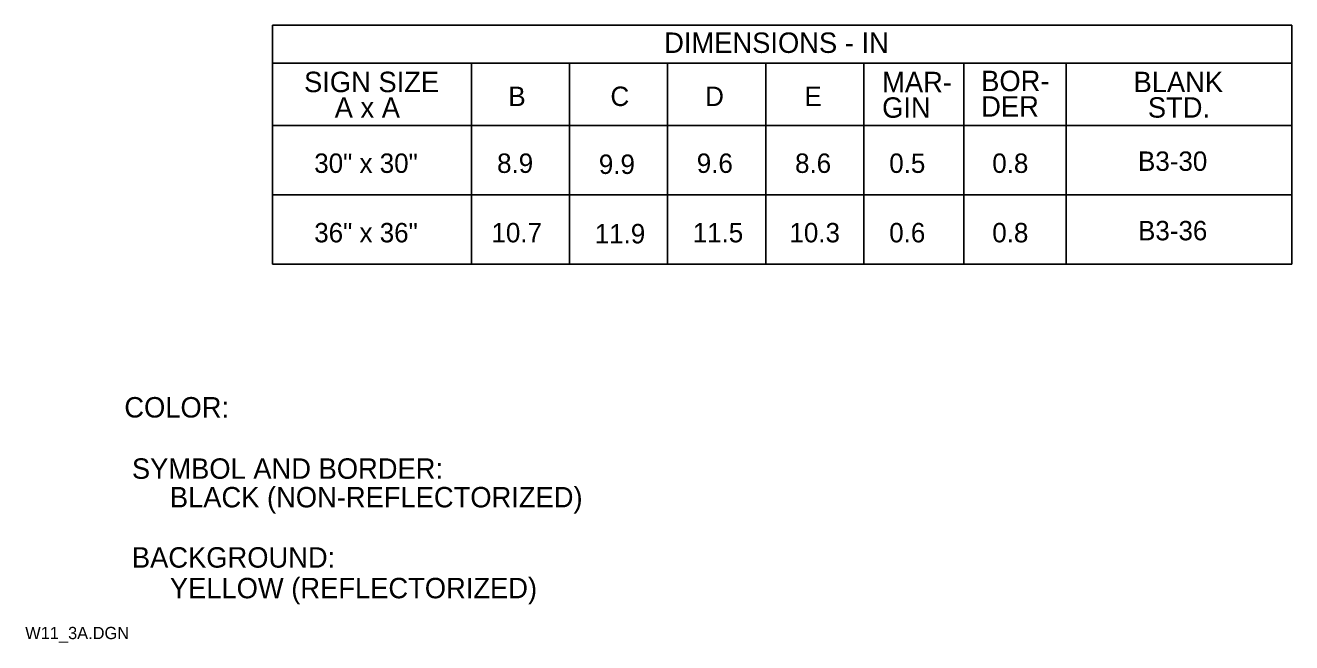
# Model space of a CAD drawing. Extents: x 0.013 to 0.184, y 0.005 to 0.259.
# Drawn here: x 0.013 to 0.168, y 0.0047 to 0.0803 of the extents above; entities that cross this region are included whole.
import ezdxf

# ---------------------------------------------------------------- set-up
doc = ezdxf.new("R2010")
doc.units = 0
doc.layers.add('1', color=7, linetype='Continuous')
doc.layers.add('3', color=7, linetype='Continuous')

msp = doc.modelspace()

# ---------------------------------------------------------------- linework, layer by layer
at = {"layer": '1'}
for p, q in [((0.168, 0.08025), (0.168, 0.051000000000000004)), ((0.12788657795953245, 0.07563878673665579), (0.12788657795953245, 0.051000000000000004)), ((0.14038657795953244, 0.07563878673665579), (0.14038657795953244, 0.051000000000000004))]:
    msp.add_line(p, q, dxfattribs=at)
at = {"layer": '3'}
for p, q in [((0.043250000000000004, 0.08025), (0.168, 0.08025)), ((0.043250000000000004, 0.08025), (0.043250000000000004, 0.051000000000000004)), ((0.168, 0.075625), (0.043250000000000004, 0.075625)), ((0.06763657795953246, 0.07563878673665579), (0.06763657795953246, 0.051000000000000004)), ((0.043250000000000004, 0.068), (0.168, 0.068)), ((0.043250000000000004, 0.059500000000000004), (0.168, 0.059500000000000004)), ((0.043250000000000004, 0.051000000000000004), (0.168, 0.051000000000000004))]:
    msp.add_line(p, q, dxfattribs=at)
for points in [[(0.079625, 0.075625), (0.079625, 0.051000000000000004)], [(0.091625, 0.075625), (0.091625, 0.051000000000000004)], [(0.10362500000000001, 0.075625), (0.10362500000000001, 0.051000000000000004)], [(0.11563657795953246, 0.07563878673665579), (0.11563657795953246, 0.051000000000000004)]]:
    msp.add_lwpolyline(points, dxfattribs=at)

# ---------------------------------------------------------------- texts
at = {"layer": '1'}
for s, height, p in [('COLOR:', 0.0024997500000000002, (0.025125, 0.03225)), (' SYMBOL AND BORDER:', 0.0024997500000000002, (0.025125, 0.02475)), ('      BLACK (NON-REFLECTORIZED)', 0.0024997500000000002, (0.025125, 0.02125)), (' BACKGROUND:', 0.0024997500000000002, (0.025125, 0.013875)), ('      YELLOW (REFLECTORIZED)', 0.0024997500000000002, (0.025125, 0.010125)), ('W11_3A.DGN', 0.0015, (0.013000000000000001, 0.005125))]:
    msp.add_text(s, height=height, dxfattribs=at).set_placement(p)
at = {"layer": '3'}
for s, height, p in [('DIMENSIONS - IN', 0.0024997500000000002, (0.09120061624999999, 0.07687374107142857)), ('SIGN SIZE', 0.0024997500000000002, (0.047125, 0.07207273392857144)), ('MAR-', 0.0024997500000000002, (0.11787500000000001, 0.07206092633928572)), ('BOR-', 0.0024997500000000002, (0.13, 0.07219836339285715)), ('BLANK', 0.0024997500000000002, (0.14864924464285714, 0.07207336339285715)), ('A x A', 0.0024997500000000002, (0.050875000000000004, 0.06894773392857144)), ('B', 0.0023752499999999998, (0.072125, 0.07037500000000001)), ('C', 0.0023752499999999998, (0.08462248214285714, 0.07037500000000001)), ('D', 0.0023752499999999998, (0.09621657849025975, 0.07037500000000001)), ('E', 0.0023752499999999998, (0.10837248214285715, 0.07037500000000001)), ('GIN', 0.0024997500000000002, (0.11787500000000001, 0.06893592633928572)), ('DER', 0.0024997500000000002, (0.13, 0.06907336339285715)), ('STD.', 0.0024997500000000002, (0.15039924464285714, 0.06894836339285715)), ('30" x 30"', 0.0023752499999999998, (0.04837041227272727, 0.062187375)), ('8.9', 0.0023752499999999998, (0.07074711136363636, 0.062187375)), ('9.9', 0.0023752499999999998, (0.08320385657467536, 0.062062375)), ('9.6', 0.0023752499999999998, (0.0951899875, 0.062187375)), ('8.6', 0.0023752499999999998, (0.10721675, 0.062187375)), ('0.5', 0.0023752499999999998, (0.1187463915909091, 0.062187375)), ('0.8', 0.0023752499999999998, (0.13135555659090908, 0.062187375)), ('B3-30', 0.0023752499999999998, (0.14919436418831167, 0.062437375)), ('36" x 36"', 0.0023752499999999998, (0.04837041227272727, 0.053687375)), ('10.7', 0.0023752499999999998, (0.07005936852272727, 0.053687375)), ('11.9', 0.0023752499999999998, (0.08270001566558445, 0.053562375)), ('11.5', 0.0023752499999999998, (0.0946890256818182, 0.053687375)), ('10.3', 0.0023752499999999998, (0.10653152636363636, 0.053687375)), ('0.6', 0.0023752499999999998, (0.1187435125, 0.053687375)), ('0.8', 0.0023752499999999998, (0.13135555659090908, 0.053687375)), ('B3-36', 0.0023752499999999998, (0.14919940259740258, 0.053937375))]:
    msp.add_text(s, height=height, dxfattribs=at).set_placement(p)

doc.saveas('drawing.dxf')
